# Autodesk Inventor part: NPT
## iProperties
Created: 2006-02
Part Number: NPT
Document SubType Name: Modeling
Designer: egolubovsky91342
Manufacturer: Standard
Standards Organization: Custom
Description: 1/16-27 NPT
Nominal_Pipe_Size: 0.06250 in
Author: egolubovsky91342
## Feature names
1. Extrusion1
2. Hole1
3. Chamfer1
